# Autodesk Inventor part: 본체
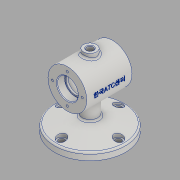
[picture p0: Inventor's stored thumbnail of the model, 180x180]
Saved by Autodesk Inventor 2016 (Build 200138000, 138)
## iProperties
Created: 2018-12
Part Number: 본체
Material: 알루미늄 6061
Document SubType Name: Modeling
Designer: 605-11
Density: 2.7 g/cm^3
Appearance: 알루미늄 - 평지
Mass: 685.082 g
Surface Area: 555.474 cm^2
Volume: 253.734 cm^3
Author: 605-11
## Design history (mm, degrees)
sketch "스케치1"
  geometry: L1 (-35, 0)-(35, 0); L2 (-35, 0)-(-35, 30); L3 (-35, 30)-(35, 30); L4 (35, 30)-(35, 0); L5 (-35, 16)-(-23, 16); L6 (-23, 16)-(-23, 14); L7 (-23, 14)-(-20, 14); L8 (-20, 14)-(-20, 25); L9 (-20, 25)-(20, 25); L10 (20, 25)-(20, 14); L11 (20, 14)-(23, 14); L12 (23, 14)-(23, 16); L13 (23, 16)-(35, 16); 2 further points
  constraints: 26 end point, 8 perpendicular, 6 point on line, 2 horizontal, 1 coincident, 1 midpoint, 1 vertical
  dimensions: "d0" = 32 diameter of L5 L1; "d1" = 28 diameter of L7 L1; "d2" = 60 diameter of L3 L1; "d3" = 50 diameter of L9 L1; "d4" = 12 distance of L5.start L5.end; "d5" = 3 distance of L6.end L7.end; "d6" = 70 distance of L2.end L3.end; "d7" = 12 distance of L12.end L13.end; "d8" = 40 distance of L8.end L9.end
revolve "회전1" sketch "스케치1" stored, may be unused: angle "d9" = 90 deg
sketch "스케치2" dims "d10" = 46
  geometry: L1 (0, 0)-(23, 0); 2 further points
  constraints: 2 coincident, 2 end point, 1 horizontal, 1 horizontal alignment, 2 other
hole "구멍1" sketch "스케치2" at (23, 0) diameter "d11" = 3.242; stored, may be unused: countersink angle "d15" = 90 deg, drill point angle "d17" = 118 deg; dims "d12" = 8, "d13" = 4, "d14" = 2, "d16" = 10
node "작업 평면1"
sketch "스케치3"
  geometry: C1 r 10 at (0, 0); 1 further point
  constraints: 1 centre point, 1 coincident
  dimensions: "d22" = 20 diameter of C1
extrude "돌출1" join sketch "스케치3" stored distance "d23" = 10; taper "d24" = 0 deg
sketch "스케치4"
  geometry: C1 r 5 at (0, 0); 1 further point
  constraints: 1 centre point, 1 coincident
  dimensions: "d25" = 10 diameter of C1
extrude "돌출2" cut sketch "스케치4" stored distance "d26" = 10; taper "d27" = 0 deg; dims "d18" = 40
chamfer "모따기1" distance "d28" = 1; stored, may be unused: second distance "d29" = 2, angle "d30" = 45 deg
fillet "모깎기1" dims "d31" = 3, "d32" = 0.3
node "작업 평면2"
sketch "스케치5"
  geometry: C1 r 55 at (0, 0); 1 further point
  constraints: 1 centre point, 1 coincident
  dimensions: "d34" = 110 diameter of C1
extrude "돌출3" join sketch "스케치5" distance "d35" = 11; taper "d36" = 0 deg
sketch "스케치6"
  geometry: C1 r 12 at (0, 0); 1 further point
  constraints: 1 centre point, 1 coincident
  dimensions: "d37" = 24 diameter of C1
extrude "돌출4" join sketch "스케치6" stored distance "d38" = 11; taper "d39" = 0 deg
sketch "스케치7"
  geometry: L1 (-24.026, 23)-(-25, 24.621) reference; L2 (-25, 24.621)-(-35, 24.621) reference; L3 (-35, 24.621)-(-35, 30) reference; L4 (-35, 30)-(-10, 30) reference; L5 (-10, 30)-(-10, 37) reference; L6 (-10, 37)-(-6, 37) reference; L7 (-6, 37)-(-5, 36) reference; L8 (-5, 36)-(-5, 25) reference; L9 (-5, 25)-(-17, 25) reference; L10 (-20, 22)-(-20, 14) reference; L11 (-20, 14)-(-23, 14) reference; L12 (-23, 14)-(-23, 15.7) reference; L13 (-23.3, 16)-(-34, 16) reference; L14 (-34, 16)-(-35, 17) reference; L15 (-35, 17)-(-35, 21.379) reference; L16 (-35, 21.379)-(-25, 21.379) reference; L17 (-25, 21.379)-(-24.026, 23) reference; L18 (24.026, -23)-(25, -24.621) reference; L19 (25, -24.621)-(35, -24.621) reference; L20 (35, -24.621)-(35, -30) reference; L21 (35, -30)-(12, -30) reference; L22 (12, -30)-(12, -64) reference; L23 (12, -64)-(55, -64) reference; L24 (55, -64)-(55, -75) reference; L25 (55, -75)-(-55, -75) reference; L26 (-55, -75)-(-55, -64) reference; L27 (-55, -64)-(-12, -64) reference; L28 (-12, -64)-(-12, -30) reference; L29 (-12, -30)-(-35, -30) reference; L30 (-35, -30)-(-35, -24.621) reference; L31 (-35, -24.621)-(-25, -24.621) reference; L32 (-25, -24.621)-(-24.026, -23) reference; L33 (-24.026, -23)-(-25, -21.379) reference; L34 (-25, -21.379)-(-35, -21.379) reference; L35 (-35, -21.379)-(-35, -17) reference; L36 (-35, -17)-(-34, -16) reference; L37 (-34, -16)-(-23.3, -16) reference; L38 (-23, -15.7)-(-23, -14) reference; L39 (-23, -14)-(-20, -14) reference; L40 (-20, -14)-(-20, -22) reference; L41 (-17, -25)-(17, -25) reference; L42 (20, -22)-(20, -14) reference; L43 (20, -14)-(23, -14) reference; L44 (23, -14)-(23, -15.7) reference; L45 (23.3, -16)-(34, -16) reference; L46 (34, -16)-(35, -17) reference; L47 (35, -17)-(35, -21.379) reference; L48 (35, -21.379)-(25, -21.379) reference; L49 (25, -21.379)-(24.026, -23) reference; L50 (25, 24.621)-(24.026, 23) reference; L51 (24.026, 23)-(25, 21.379) reference; L52 (25, 21.379)-(35, 21.379) reference; L53 (35, 21.379)-(35, 17) reference; L54 (35, 17)-(34, 16) reference; L55 (34, 16)-(23.3, 16) reference; L56 (23, 15.7)-(23, 14) reference; L57 (23, 14)-(20, 14) reference; L58 (20, 14)-(20, 22) reference; L59 (17, 25)-(5, 25) reference; L60 (5, 25)-(5, 36) reference; L61 (5, 36)-(6, 37) reference; L62 (6, 37)-(10, 37) reference; L63 (10, 37)-(10, 30) reference; L64 (10, 30)-(35, 30) reference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; A1 r 3 centre (-17, 22) between (-17, 25) and (-20, 22) reference; A2 r 0.3 centre (-23.3, 15.7) between (-23, 15.7) and (-23.3, 16) reference; A3 r 0.3 centre (-23.3, -15.7) between (-23.3, -16) and (-23, -15.7) reference; A4 r 3 centre (-17, -22) between (-20, -22) and (-17, -25) reference; A5 r 3 centre (17, -22) between (17, -25) and (20, -22) reference; A6 r 0.3 centre (23.3, -15.7) between (23, -15.7) and (23.3, -16) reference; A7 r 0.3 centre (23.3, 15.7) between (23.3, 16) and (23, 15.7) reference; A8 r 3 centre (17, 22) between (20, 22) and (17, 25) reference
  constraints: 4 end point, 1 midpoint, 1 point on line
  dimensions: "d40" = 75 deg angle of L24 L67
revolve "회전2" sketch "스케치7" stored, may be unused: angle "d41" = 90 deg
fillet "모깎기2" dims "d42" = 3
sketch "스케치8" dims "d43" = 88
  geometry: L1 (0, 0)-(44, 0); 2 further points
  constraints: 2 coincident, 2 end point, 1 horizontal, 1 horizontal alignment, 2 other
hole "구멍2" sketch "스케치8" at (44, 0) diameter "d44" = 9; stored, may be unused: countersink angle "d48" = 90 deg, drill point angle "d50" = 118 deg; dims "d45" = 6, "d46" = 4, "d47" = 2, "d49" = 10
node "작업 평면3"
sketch "스케치9" dims "d52" = 88
  geometry: L1 (0, 0)-(44, 0); C1 r 14.224 at (0, 0) reference; C2 r 52.776 at (0, 0) reference; C3 r 7 at (44, 0); 4 further points
  constraints: 2 coincident, 2 end point, 1 centre point, 1 horizontal, 1 horizontal alignment, 4 other
  dimensions: "d53" = 14 diameter of C3
extrude "돌출5" cut sketch "스케치9" stored distance "d54" = 10; taper "d55" = 0 deg
node "작업 평면4"
sketch "스케치10"
  geometry: L1 (-35, -30)-(-35, 30) reference; 2 further points
  constraints: 1 coincident, 1 other
feature "엠보싱1" sketch "스케치10" dims "d13" = 4, "d61" = 0.5, "d62" = 0
node "솔리드1"
pattern_circular "원형 패턴1" dims angle "d19" = 360 deg
mirror "대칭1"
pattern_circular "원형 패턴2" dims angle "d57" = 360 deg
node "투영된 루프1"
node "절단 모서리 투영1"
other parameters: "d21" = 37, "d33" = -75, "d59" = -77.5
